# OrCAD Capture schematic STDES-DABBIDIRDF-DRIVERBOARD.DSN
size E
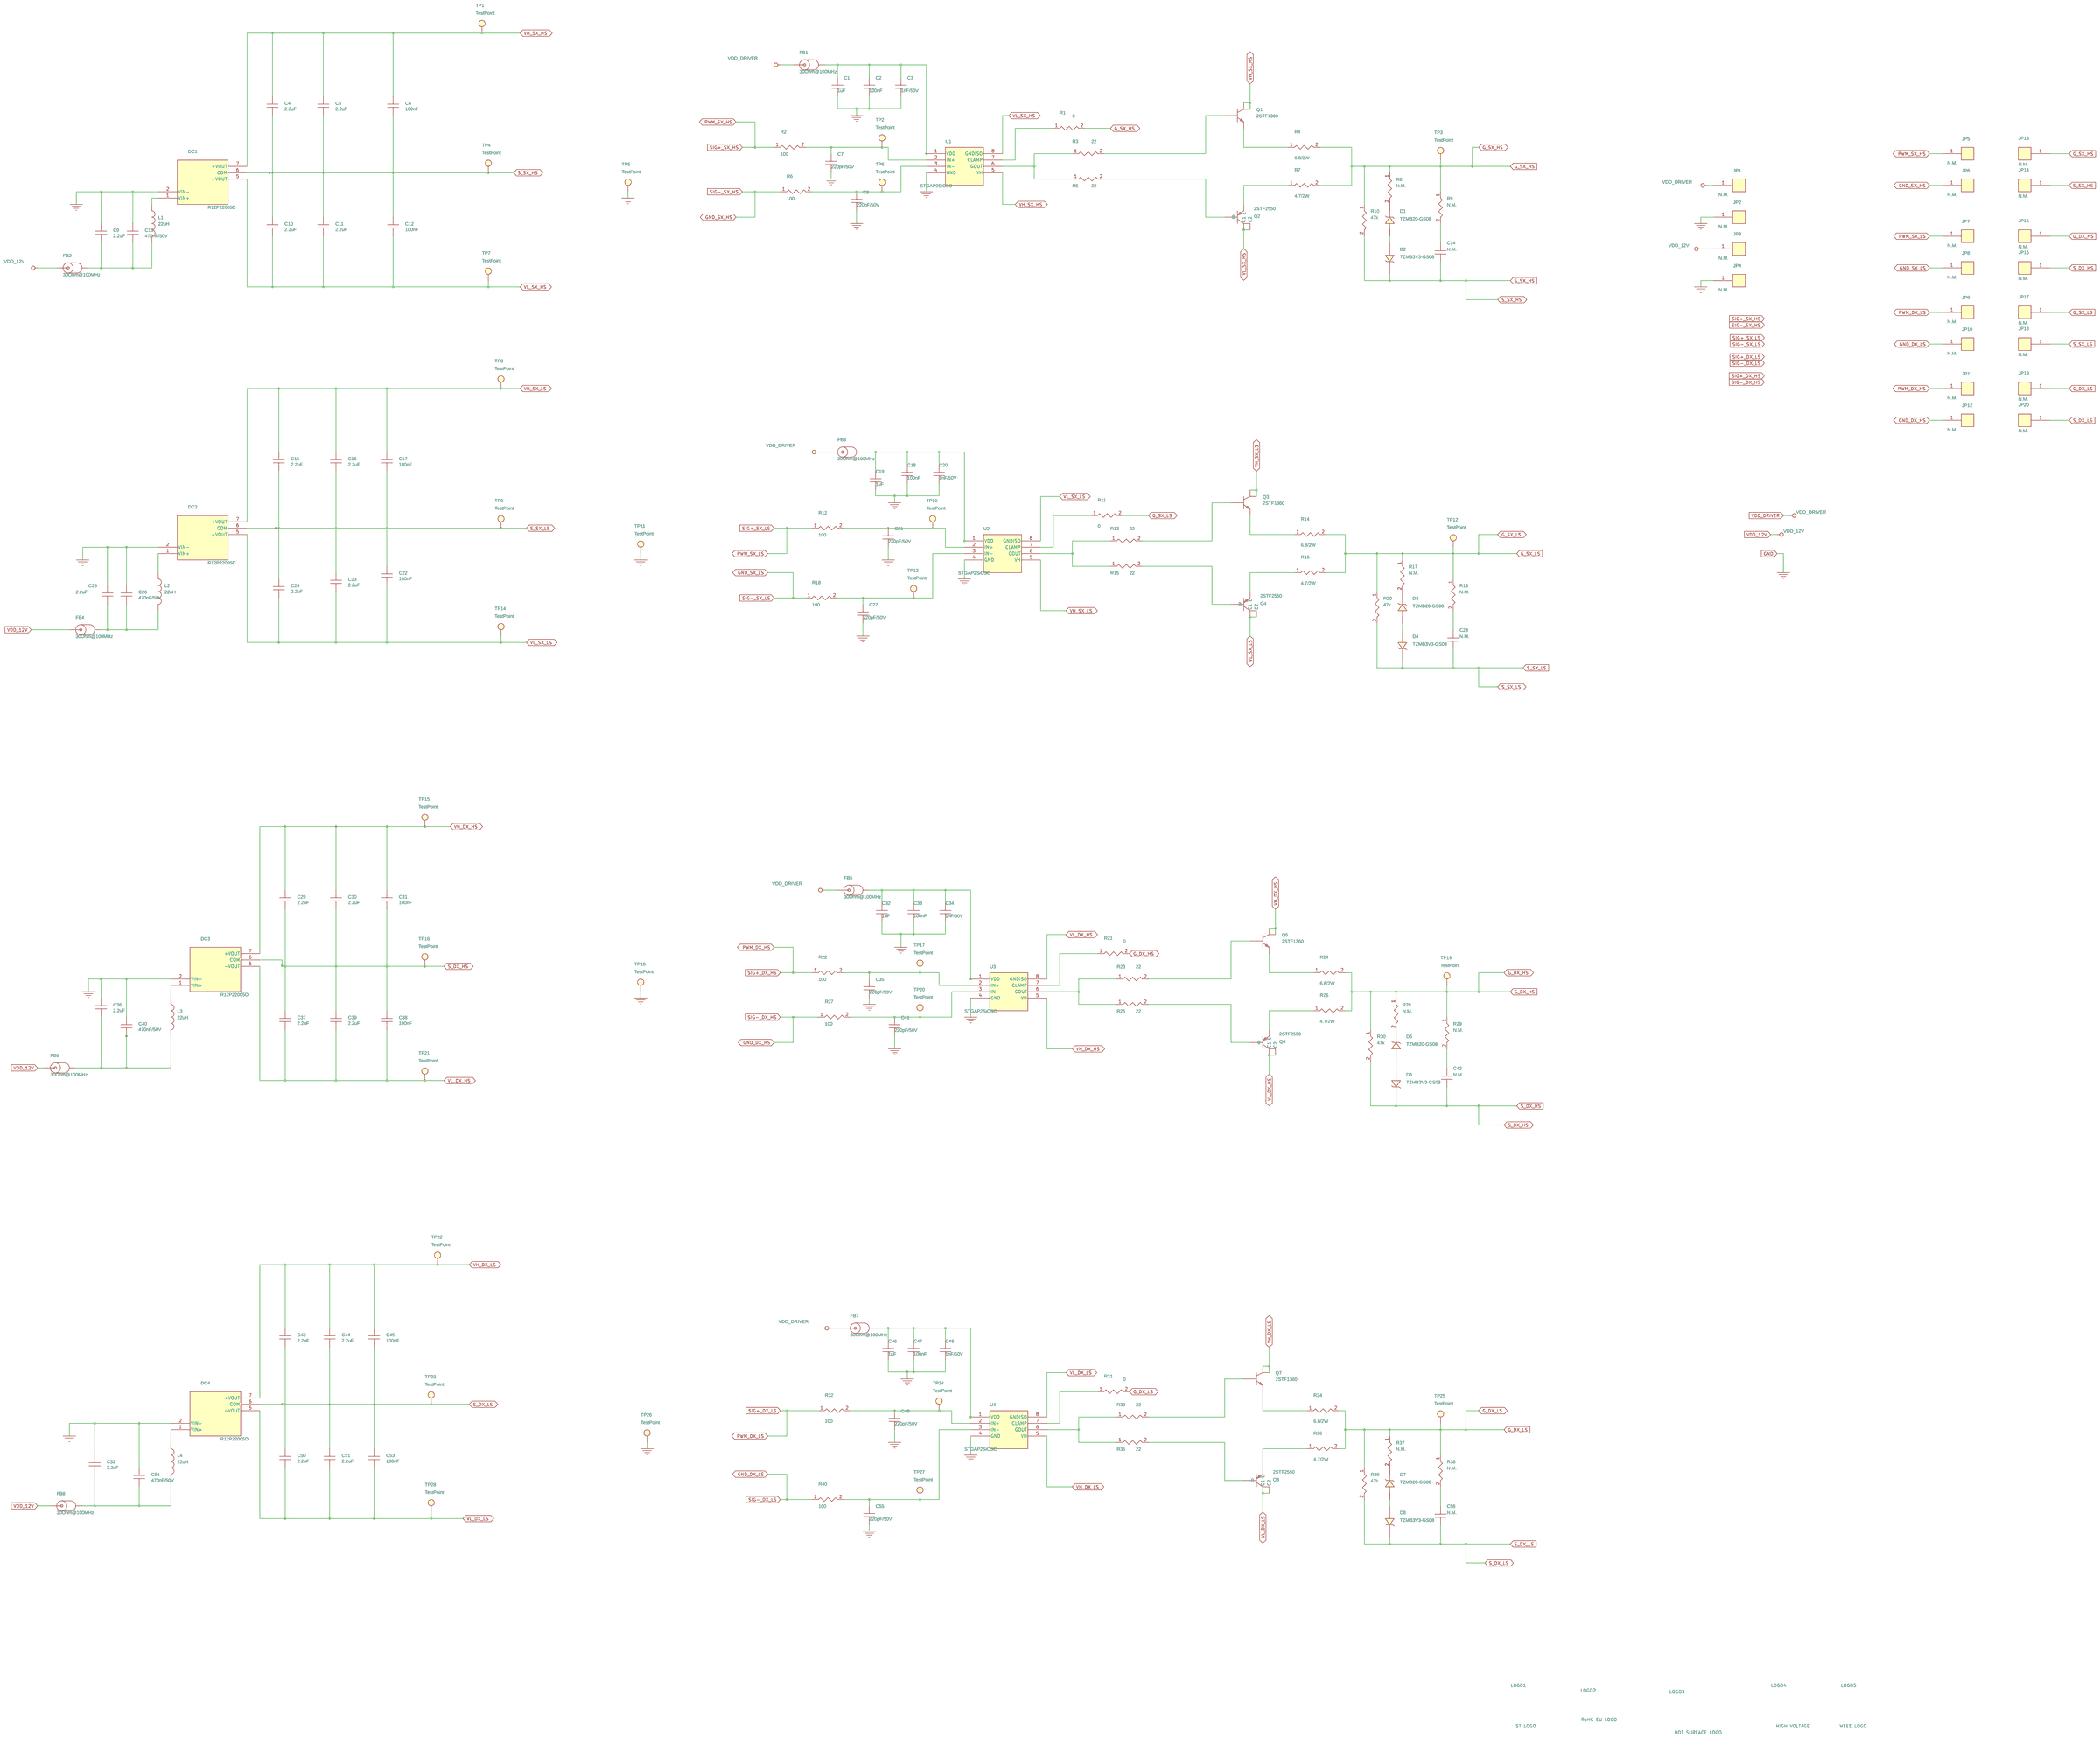
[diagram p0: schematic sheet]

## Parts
C1  1uF  [C_0603]
C2  100nF  [C_0603]
C3  1nF/50V  [C_0603]
C4  2.2uF  [C_0805]
C5  2.2uF  [C_0805]
C6  100nF  [C_0603]
C7  220pF/50V  [C_0603]
C8  220pF/50V  [C_0603]
C9  2.2uF  [C_0805]
C10  2.2uF  [C_0805]
C11  2.2uF  [C_0805]
C12  100nF  [C_0603]
C13  470nF/50V  [C_0805]
C14  N.M.  [C_0603]
C15  2.2uF  [C_0805]
C16  2.2uF  [C_0805]
C17  100nF  [C_0603]
C18  100nF  [C_0603]
C19  1uF  [C_0603]
C20  1nF/50V  [C_0603]
C21  220pF/50V  [C_0603]
C22  100nF  [C_0603]
C23  2.2uF  [C_0805]
C24  2.2uF  [C_0805]
C25  2.2uF  [C_0805]
C26  470nF/50V  [C_0805]
C27  220pF/50V  [C_0603]
C28  N.M.  [C_0603]
C29  2.2uF  [C_0805]
C30  2.2uF  [C_0805]
C31  100nF  [C_0603]
C32  1uF  [C_0603]
C33  100nF  [C_0603]
C34  1nF/50V  [C_0603]
C35  220pF/50V  [C_0603]
C36  2.2uF  [C_0805]
C37  2.2uF  [C_0805]
C38  100nF  [C_0603]
C39  2.2uF  [C_0805]
C40  470nF/50V  [C_0805]
C41  220pF/50V  [C_0603]
C42  N.M.  [C_0603]
C43  2.2uF  [C_0805]
C44  2.2uF  [C_0805]
C45  100nF  [C_0603]
C46  1uF  [C_0603]
C47  100nF  [C_0603]
C48  1nF/50V  [C_0603]
C49  220pF/50V  [C_0603]
C50  2.2uF  [C_0805]
C51  2.2uF  [C_0805]
C52  2.2uF  [C_0805]
C53  100nF  [C_0603]
C54  470nF/50V  [C_0805]
C55  220pF/50V  [C_0603]
C56  N.M.  [C_0603]
D1  TZMB20-GS08  [DIODE_DO-213AC_SOD-80]
D2  TZMB3V3-GS08  [DIODE_DO-213AC_SOD-80]
D3  TZMB20-GS08  [DIODE_DO-213AC_SOD-80]
D4  TZMB3V3-GS08  [DIODE_DO-213AC_SOD-80]
D5  TZMB20-GS08  [DIODE_DO-213AC_SOD-80]
D6  TZMB3V3-GS08  [DIODE_DO-213AC_SOD-80]
D7  TZMB20-GS08  [DIODE_DO-213AC_SOD-80]
D8  TZMB3V3-GS08  [DIODE_DO-213AC_SOD-80]
DC1  R12P22005D  [DCDC_Recom_RxxP2]
DC2  R12P22005D  [DCDC_Recom_RxxP2]
DC3  R12P22005D  [DCDC_Recom_RxxP2]
DC4  R12P22005D  [DCDC_Recom_RxxP2]
FB1  30Ohm@100MHz  [L_0805]
FB2  30Ohm@100MHz  [L_0805]
FB3  30Ohm@100MHz  [L_0805]
FB4  30Ohm@100MHz  [L_0805]
FB5  30Ohm@100MHz  [L_0805]
FB6  30Ohm@100MHz  [L_0805]
FB7  30Ohm@100MHz  [L_0805]
FB8  30Ohm@100MHz  [L_0805]
JP1  N.M.  [3560-1-00-15-00-00-03-0]
JP2  N.M.  [3560-1-00-15-00-00-03-0]
JP3  N.M.  [3560-1-00-15-00-00-03-0]
JP4  N.M.  [3560-1-00-15-00-00-03-0]
JP5  N.M.  [3560-1-00-15-00-00-03-0]
JP6  N.M.  [3560-1-00-15-00-00-03-0]
JP7  N.M.  [3560-1-00-15-00-00-03-0]
JP8  N.M.  [3560-1-00-15-00-00-03-0]
JP9  N.M.  [3560-1-00-15-00-00-03-0]
JP10  N.M.  [3560-1-00-15-00-00-03-0]
JP11  N.M.  [3560-1-00-15-00-00-03-0]
JP12  N.M.  [3560-1-00-15-00-00-03-0]
JP13  N.M.  [3560-1-00-15-00-00-03-0]
JP14  N.M.  [3560-1-00-15-00-00-03-0]
JP15  N.M.  [3560-1-00-15-00-00-03-0]
JP16  N.M.  [3560-1-00-15-00-00-03-0]
JP17  N.M.  [3560-1-00-15-00-00-03-0]
JP18  N.M.  [3560-1-00-15-00-00-03-0]
JP19  N.M.  [3560-1-00-15-00-00-03-0]
JP20  N.M.  [3560-1-00-15-00-00-03-0]
L1  22uH  [L_0805]
L2  22uH  [L_0805]
L3  22uH  [L_0805]
L4  22uH  [L_0805]
LOGO1  ST LOGO  [STLogo12mm]
LOGO2  RoHS EU LOGO  [rohs-eu-logo13mm]
LOGO3  HOT SURFACE LOGO  [Hot-Surface-Logo8mm]
LOGO4  HIGH VOLTAGE  [High-Voltage-Logo10mm]
LOGO5  WEEE LOGO  [weee12mm]
Q1  2STF1360  [sot89-4p142_409x160l104x50n]
Q2  2STF2550  [sot89-4p142_409x160l104x50n]
Q3  2STF1360  [sot89-4p142_409x160l104x50n]
Q4  2STF2550  [sot89-4p142_409x160l104x50n]
Q5  2STF1360  [sot89-4p142_409x160l104x50n]
Q6  2STF2550  [sot89-4p142_409x160l104x50n]
Q7  2STF1360  [sot89-4p142_409x160l104x50n]
Q8  2STF2550  [sot89-4p142_409x160l104x50n]
R1  0  [r_1210]
R2  100  [r_0603]
R3  22  [r_1210]
R4  6.8/2W  [r_2512]
R5  22  [r_1210]
R6  100  [r_0603]
R7  4.7/2W  [r_2512]
R8  N.M.  [r_0603]
R9  N.M.  [r_0603]
R10  47k  [r_0603]
R11  0  [r_1206]
R12  100  [r_0603]
R13  22  [r_1210]
R14  6.8/2W  [r_2512]
R15  22  [r_1210]
R16  4.7/2W  [r_2512]
R17  N.M.  [r_0603]
R18  100  [r_0603]
R19  N.M.  [r_0603]
R20  47k  [r_0603]
R21  0  [r_1210]
R22  100  [r_0603]
R23  22  [r_1210]
R24  6.8/2W  [r_2512]
R25  22  [r_1210]
R26  4.7/2W  [r_2512]
R27  100  [r_0603]
R28  N.M.  [r_0603]
R29  N.M.  [r_0603]
R30  47k  [r_0603]
R31  0  [r_1210]
R32  100  [r_0603]
R33  22  [r_1210]
R34  6.8/2W  [r_2512]
R35  22  [r_1210]
R36  4.7/2W  [r_2512]
R37  N.M.  [r_0603]
R38  N.M.  [r_0603]
R39  47k  [r_0603]
R40  100  [r_0603]
TP1  TestPoint  [testpointd100red]
TP2  TestPoint  [testpointd100red]
TP3  TestPoint  [testpointd100red]
TP4  TestPoint  [testpointd100red]
TP5  TestPoint  [testpointd100red]
TP6  TestPoint  [testpointd100red]
TP7  TestPoint  [testpointd100red]
TP8  TestPoint  [testpointd100red]
TP9  TestPoint  [testpointd100red]
TP10  TestPoint  [testpointd100red]
TP11  TestPoint  [testpointd100red]
TP12  TestPoint  [testpointd100red]
TP13  TestPoint  [testpointd100red]
TP14  TestPoint  [testpointd100red]
TP15  TestPoint  [testpointd100red]
TP16  TestPoint  [testpointd100red]
TP17  TestPoint  [testpointd100red]
TP18  TestPoint  [testpointd100red]
TP19  TestPoint  [testpointd100red]
TP20  TestPoint  [testpointd100red]
TP21  TestPoint  [testpointd100red]
TP22  TestPoint  [testpointd100red]
TP23  TestPoint  [testpointd100red]
TP24  TestPoint  [testpointd100red]
TP25  TestPoint  [testpointd100red]
TP26  TestPoint  [testpointd100red]
TP27  TestPoint  [testpointd100red]
TP28  TestPoint  [testpointd100red]
U1  STGAP2SiCSC  [soic8p127_584x1031x264l76x40n]
U2  STGAP2SiCSC  [soic8p127_584x1031x264l76x40n]
U3  STGAP2SiCSC  [soic8p127_584x1031x264l76x40n]
U4  STGAP2SiCSC  [soic8p127_584x1031x264l76x40n]

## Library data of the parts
C1 C19 C32 C46 = CAP: CAPACITOR CERAMIC SMD 0603; ALT_SYMBOLS: c_0603_hd; Any Equivalent?: YES; CLASS: DISCRETE; Dielectric Type: Capacitors; Manufacturer: Wurth Electronics Inc.; Manufacturer PN: 885012206076; PART_NUMBER: CAP-00000064; Package Size: 0603 (1608 Metric); Rated Voltage: 25V; Tolerance: 10%
C2 C18 C33 C47 = CAP: CAPACITOR CERAMIC SMD 0603; ALT_SYMBOLS: c_0603_hd; Any Equivalent?: YES; CLASS: DISCRETE; Dielectric Type: Capacitors; Manufacturer: Wurth Electronics Inc.; Manufacturer PN: 885012206095; Package Size: 0603 (1608 Metric); Rated Voltage: 50V; Tolerance: 10%
C3 C20 C34 C48 = CAP: CAPACITOR CERAMIC SMD 0603; ALT_SYMBOLS: c_0603_hd; Any Equivalent?: YES; CLASS: DISCRETE; Dielectric Type: Capacitors; Manufacturer: Wurth Electronics Inc.; Manufacturer PN: 885012006063; PART_NUMBER: CAP-00000064; Package Size: 0603 (1608 Metric); Rated Voltage: 50V; Tolerance: 5%
C4 C5 C9-C11 C15 C16 C23-C25 C29 C30 C36 C37 C39 C43 C44 C50-C52 = CAP: CAPACITOR CERAMIC SMD 0805; Any Equivalent?: YES; CLASS: DISCRETE; Dielectric Type: Capacitors; Manufacturer: Wurth Electronics Inc.; Manufacturer PN: 885012207079; PART_NUMBER: CAP-00000034; Package Size: 0805 (2012 Metric); Rated Voltage: 25V; Temperature Coefficient: X7R; Tolerance: 10%
C6 C12 C17 C22 C31 C38 C45 C53 = CAP: CAPACITOR CERAMIC SMD 0603; Any Equivalent?: YES; CLASS: DISCRETE; Dielectric Type: Capacitors; Manufacturer: Wurth Electronics Inc.; Manufacturer PN: 885012206095; Package Size: 0603 (1608 Metric); Rated Voltage: 50V; Temperature Coefficient: X7R; Tolerance: 10%
C7 C8 C21 C27 C35 C41 C49 C55 = CAP: CAPACITOR CERAMIC SMD 0603; ALT_SYMBOLS: c_0603_hd; Any Equivalent?: YES; CLASS: DISCRETE; Dielectric Type: Capacitors; Manufacturer: Wurth Electronics Inc.; Manufacturer PN: 885012006059; PART_NUMBER: CAP-00000064; Package Size: 0603 (1608 Metric); Rated Voltage: 50V; Tolerance: 5%
C13 C26 C40 C54 = CAP: CAPACITOR CERAMIC SMD 0805; ALT_SYMBOLS: C_0805_hd; Any Equivalent?: YES; CLASS: DISCRETE; Dielectric Type: Capacitors; Manufacturer: Wurth Electronics Inc.; Manufacturer PN: 885012207102; PART_NUMBER: CAP-00000192; Package Size: 0805 (2012 Metric); Rated Voltage: 50V; Tolerance: 5%
C14 C28 C42 C56 = CAP_NP: Manufacturer: ANY; Manufacturer code: ANY; Package: 0603; Tecnology: X7R Ceramic Capacitor
D1 D3 D5 D7 = DIODE_ZENER: DIODE ZENER 20V 500MW SOD80; Any Equivalent?: YES; CLASS: DISCRETE; Manufacturer: Vishay Semiconductor Diodes Division; PART_NUMBER: TMP-670; Package Size: DO-213AC, MINI-MELF, SOD-80
D2 D4 D6 D8 = DIODE_ZENER: DIODE ZENER 3.3V 500MW SOD80; Any Equivalent?: YES; CLASS: DISCRETE; Manufacturer: Vishay Semiconductor Diodes Division; PART_NUMBER: TMP-671; Package Size: DO-213AC, MINI-MELF, SOD-80
DC1-DC4 = DCDC_Recom_RxxP2: CONV DC/DC 2W 12VIN +20/-5VOUT T; Any Equivalent?: NO; CLASS: IC; Manufacturer: Recom Power; PART_NUMBER: IC-00000050; Package Size: 0.77" L x 0.39" W x 0.49" H (19.5mm x 9.8mm x 12.5mm)
FB1-FB8 = IND_FB: FERRITE BEAD 30 OHM 0805 1LN; Any Equivalent?: NO; CLASS: DISCRETE; Manufacturer: Wurth Electronics Inc.; Manufacturer PN: 74279206; PART_NUMBER: IND-00000001; Package Size: 0805 (2012 Metric)
JP1-JP20 = 3560-1-00-15-00-00-03-0: IC & Component Sockets .060" Dia St Pins; Manufacturer: Mill-Max
L1-L4 = IND: FIXED IND 22UH 130MA 3.7 OHM SMD; Any Equivalent?: YES; CLASS: DISCRETE; Manufacturer: Taiyo Yuden; Manufacturer PN: LBC2012T220M; PART_NUMBER: IND-00000051; Package Size: 0805 (2012 Metric); Tolerance: 20%
LOGO1 = LOGO_ST: ST LOGO - SILKSCREEN; ALT_SYMBOLS: stlogo11mm,STLogo10mm,STLogo9mm,STLogo8mm,STLogo7mm,STLogo6mm,STLogo5mm,stlogo4mm; CLASS: Mechanical; PART_NUMBER: MECH-00000001
LOGO2 = RoHS_EU: RoHS EU - SILKSCREEN; ALT_SYMBOLS: rohs-eu-logo9mm,RoHS-Eu-Logo7mm,RoHS-Eu-Logo5mm; Any Equivalent?: NOT; CLASS: Mechanical; PART_NUMBER: MIS-00000007
LOGO3 = LOGO_HOT_SURFACE: HOT SURFACE LOGO - SILKSCREEN; ALT_SYMBOLS: Hot-Surface-Logo10mm,Hot-Surface-Logo12mm; Any Equivalent?: NO; CLASS: Mechanical; PART_NUMBER: MIS-00000011
LOGO4 = HIGH_VOLTAGE: HIGH VOLTAGE LOGO - SILKSCREEN; ALT_SYMBOLS: high-voltage-logo7mm,HIGH-VOLTAGE-LOGO6MM,high-voltage-logo5mm,High-Voltage-Text-Logo; Any Equivalent?: NO; CLASS: Mechanical; PART_NUMBER: MIS-00000028
LOGO5 = WEEE: WEEE LOGO - SILKSCREEN; ALT_SYMBOLS: weee10mm,weee8mm,weee7mm; CLASS: Mechanical; PART_NUMBER: LOGO-00000001
Q1 Q3 Q5 Q7 = BJT_NPN_BCEC_4P: TRANS NPN 60V 3A SOT-89; Any Equivalent?: NO; CLASS: DISCRETE; Manufacturer: STMicroelectronics; PART_NUMBER: TMP-669; Package Size: TO-243AA; Polarity: NPN
Q2 Q4 Q6 Q8 = BJT_PNP_BCEC_4P: TRANS PNP 50V 5A SOT 89; Any Equivalent?: NO; CLASS: DISCRETE; Manufacturer: STMicroelectronics; PART_NUMBER: TMP-695; Package Size: TO-243AA; Polarity: PNP
R1 R3 R5 R13 R15 R21 R23 R25 R31 R33 R35 = RES: CHIP RESISTOR SMD; Any Equivalent?: YES; Manufacturer: ANY; Manufacturer PN: ANY; PART_NUMBER: Gen_R-000006; Package Size: 1210 (3225 Metric)
R2 R6 R8-R10 R12 R17-R20 R22 R27-R30 R32 R37-R40 = RES: CHIP RESISTOR SMD 1% 1/10W 0603; ALT_SYMBOLS: r_0603_hd; Any Equivalent?: YES; Manufacturer: ANY; Manufacturer PN: ANY; PART_NUMBER: Gen_R-000003; Package Size: 0603 (1608 Metric); Rated Power: 0.1W, 1/10W; Tolerance: 1%
R4 R7 R14 R16 R24 R26 R34 R36 = RES: CHIP RESISTOR SMD; Any Equivalent?: YES; Manufacturer: ANY; Manufacturer PN: ANY; PART_NUMBER: Gen_R-000008; Package Size: 2512 (6332 metric); Rated Power: 2W
R11 = RES: CHIP RESISTOR SMD 5% 1/4W 1206; ALT_SYMBOLS: r_1206_hd; Any Equivalent?: YES; CLASS: DISCRETE; Manufacturer: ANY; Manufacturer PN: ANY; PART_NUMBER: RES-00000102; Package Size: 1206 (3216 Metric); Rated Power: 0.25W, 1/4W; STEP_MODEL: R_1206; Tolerance: 5%
TP1-TP28 = TESTPOINT: TEST POINT PC MINI .040"D RED; Any Equivalent?: YES; CLASS: IO; Manufacturer: ANY; Manufacturer PN: ANY; PART_NUMBER: CON-00000188; Package Size: 0.100" Dia x 0.180" L (2.54mm x 4.57mm)
U1-U4 = STGAP2SiCSC: Galvanically isolated 4 A single gate driver for SiC MOSFETs; Any Equivalent?: NO; CLASS: IC; Manufacturer: STMicroelectronics; PART_NUMBER: IC-00000131; STEP_MODEL: SOIC8P127_584X1031X264L76X40

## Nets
GND: C1.2 C2.2 C3.2 C7.2 C8.2 C9.1 C13.1 C18.2 C19.2 C20.2 C21.2 C25.1 C26.1 C27.2 C32.2 C33.2 C34.2 C35.2 C36.1 C40.1 C41.2 C46.2 C47.2 C48.2 C49.2 C52.1 C54.1 C55.2 DC1.2(VIN-) DC2.2(VIN-) DC3.2(VIN-) DC4.2(VIN-) JP2.1 JP4.1 TP5.1 TP11.1 TP18.1 TP26.1 U1.4(GND) U2.4(GND) U3.4(GND) U4.4(GND)
GND_DX_HS: JP12.1 R27.1
GND_DX_LS: JP10.1 R40.1
GND_SX_HS: JP6.1 R6.1
GND_SX_LS: JP8.1 R18.1
VDD_12V: FB2.1 FB4.1 FB6.1 FB8.1 JP3.1
VDD_DRIVER: FB1.1 FB3.1 FB5.1 FB7.1 JP1.1
G_DX_HS: JP15.1 R21.2 R24.2 R26.2 R28.1 R29.1 R30.1 TP19.1
G_DX_LS: JP19.1 R31.2 R34.2 R36.2 R37.1 R38.1 R39.1 TP25.1
G_SX_HS: JP13.1 R1.2 R4.2 R7.2 R8.1 R9.1 R10.1 TP3.1
G_SX_LS: JP17.1 R11.2 R14.2 R16.2 R17.1 R19.1 R20.1 TP12.1
PWM_DX_HS: JP11.1 R22.1
PWM_DX_LS: JP9.1 R32.1
PWM_SX_HS: JP5.1 R2.1
PWM_SX_LS: JP7.1 R12.1
S_DX_HS: C29.2 C30.2 C31.2 C37.1 C38.1 C39.1 C42.1 D6.C DC3.6(COM) JP16.1 R30.2 TP16.1
S_DX_LS: C43.2 C44.2 C45.2 C50.1 C51.1 C53.1 C56.1 D8.C DC4.6(COM) JP20.1 R39.2 TP23.1
S_SX_HS: C4.2 C5.2 C6.2 C10.1 C11.1 C12.1 C14.1 D2.C DC1.6(COM) JP14.1 R10.2 TP4.1
S_SX_LS: C15.2 C16.2 C17.2 C22.1 C23.1 C24.1 C28.1 D4.C DC2.6(COM) JP18.1 R20.2 TP9.1
VH_DX_HS: C29.1 C30.1 C31.1 DC3.7(+VOUT) Q5.2(C1) Q5.4(C) TP15.1 U3.5(VH)
VH_DX_LS: C43.1 C44.1 C45.1 DC4.7(+VOUT) Q7.2(C1) Q7.4(C) TP22.1 U4.5(VH)
VH_SX_HS: C4.1 C5.1 C6.1 DC1.7(+VOUT) Q1.2(C1) Q1.4(C) TP1.1 U1.5(VH)
VH_SX_LS: C15.1 C16.1 C17.1 DC2.7(+VOUT) Q3.2(C1) Q3.4(C) TP8.1 U2.5(VH)
VL_DX_HS: C37.2 C38.2 C39.2 DC3.5(-VOUT) Q6.2(C1) Q6.4(C2) TP21.1 U3.8(GNDISO)
VL_DX_LS: C50.2 C51.2 C53.2 DC4.5(-VOUT) Q8.2(C1) Q8.4(C2) TP28.1 U4.8(GNDISO)
VL_SX_HS: C10.2 C11.2 C12.2 DC1.5(-VOUT) Q2.2(C1) Q2.4(C2) TP7.1 U1.8(GNDISO)
VL_SX_LS: C22.2 C23.2 C24.2 DC2.5(-VOUT) Q4.2(C1) Q4.4(C2) TP14.1 U2.8(GNDISO)
N16765017: C1.1 C2.1 C3.1 FB1.2 U1.1(VDD)
N16765409: R1.1 U1.7(CLAMP)
N16765429: C7.1 R2.2 TP2.1 U1.2(IN+)
N16765547: R3.1 R5.1 U1.6(GOUT)
N16765555: Q1.1(B) R3.2
N16765661: C8.1 R6.2 TP6.1 U1.3(IN-)
N16765857: Q2.1(B) R5.2
N16766145: C14.2 R9.2
N16766205: D1.A D2.A
N16766209: C9.2 C13.2 FB2.2 L1.2
N16766605: C18.1 C19.1 C20.1 FB3.2 U2.1(VDD)
N16766995: R11.1 U2.7(CLAMP)
N16767019: C27.1 R18.2 TP13.1 U2.3(IN-)
N16767137: R13.1 R15.1 U2.6(GOUT)
N16767145: Q3.1(B) R13.2
N16767193: C21.1 R12.2 TP10.1 U2.2(IN+)
N16767217: DC2.1(VIN+) L2.1
N16767383: Q4.1(B) R15.2
N16767595: C25.2 C26.2 FB4.2 L2.2
N16767699: C28.2 R19.2
N16767741: D3.A D4.A
N16781074: C46.1 C47.1 C48.1 FB7.2 U4.1(VDD)
N16781268: R31.1 U4.7(CLAMP)
N16781280: C55.1 R40.2 TP27.1 U4.3(IN-)
N16781339: R33.1 R35.1 U4.6(GOUT)
N16781343: Q7.1(B) R33.2
N16781367: C49.1 R32.2 TP24.1 U4.2(IN+)
N16781378: DC4.1(VIN+) L4.1
N16781461: Q8.1(B) R35.2
N16781568: C52.2 C54.2 FB8.2 L4.2
N16781606: C56.2 R38.2
N16781636: D7.A D8.A
N16782046: C32.1 C33.1 C34.1 FB5.2 U3.1(VDD)
N16782240: R21.1 U3.7(CLAMP)
N16782252: C35.1 R22.2 TP17.1 U3.2(IN+)
N16782311: R23.1 R25.1 U3.6(GOUT)
N16782315: Q5.1(B) R23.2
N16782339: C41.1 R27.2 TP20.1 U3.3(IN-)
N16782350: DC3.1(VIN+) L3.1
N16782433: Q6.1(B) R25.2
N16782538: C36.2 C40.2 FB6.2 L3.2
N16782578: C42.2 R29.2
N16782608: D5.A D6.A
N16811921: DC1.1(VIN+) L1.1
N16851729: Q3.3(E) R14.1
N16851734: Q4.3(E) R16.1
N16855550: Q1.3(E) R4.1
N16855582: Q2.3(E) R7.1
N16856448: Q7.3(E) R34.1
N16856478: Q8.3(E) R36.1
N16858249: Q5.3(E) R24.1
N16858287: Q6.3(E) R26.1
N16887993: D1.C R8.2
N16888285: D3.C R17.2
N16888286: D7.C R37.2
N16888287: D5.C R28.2
